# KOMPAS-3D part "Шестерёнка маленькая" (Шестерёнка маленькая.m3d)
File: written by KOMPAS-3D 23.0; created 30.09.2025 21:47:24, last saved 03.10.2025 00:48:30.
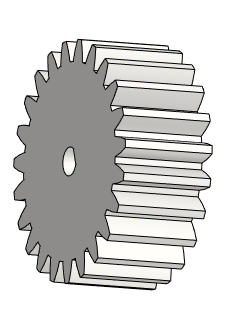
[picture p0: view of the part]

Document properties: Автор: Inspektor_Kot; Полное имя файла: I:\Autodesk Inventor Projects\ИМ-ИТ ЦД\Вариант 11\Шестерёнка маленькая.m3d

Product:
- Part/product: Шестерёнка маленькая
    Масса: 0.256368

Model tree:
1. Операция без истории:1
2. Эскиз:1  (with: Операция без истории:1)
3. Элемент выдавливания:1
     Расстояние 2 = 20
4. Эскиз:2  (with: Операция без истории:1)
5. Элемент выдавливания:2
     Расстояние 2 = 20
6. Эскиз:3  (with: Операция без истории:1, Элемент выдавливания:2)
7. Элемент выдавливания:3
     Расстояние 2 = 3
